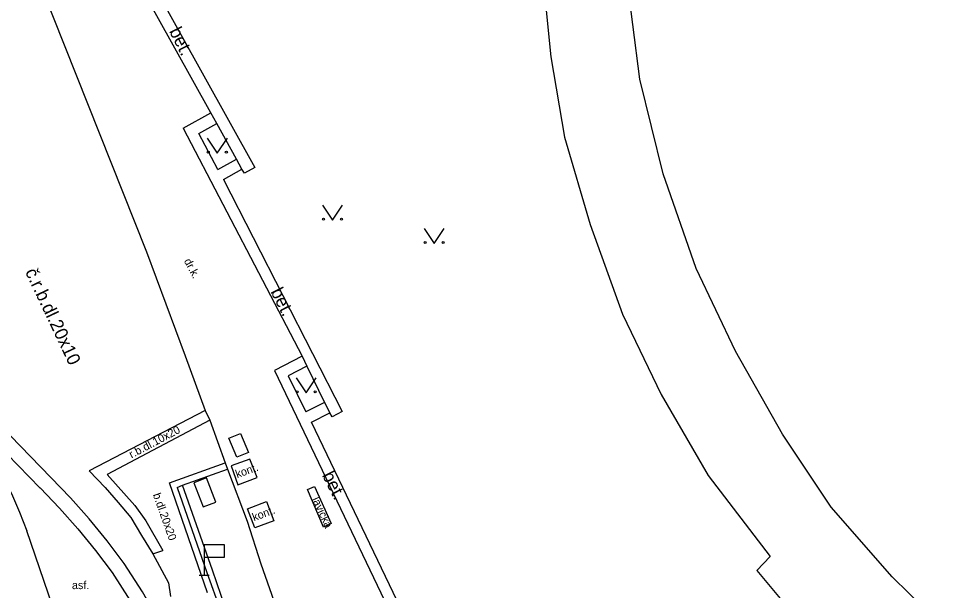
# Model space of a CAD drawing. Extents: x -600391 to -599491, y -1160176 to -1159402.
# Drawn here: x -599963.68 to -599916.73, y -1159762.76 to -1159734.28 of the extents above; entities that cross this region are included whole.
import ezdxf

# ---------------------------------------------------------------- set-up
doc = ezdxf.new("R2010")
doc.units = 0
for name, color, linetype in [('Level 10', 7, 'Continuous'), ('Level 11', 7, 'Continuous'), ('Level 13', 7, 'Continuous'), ('Level 24', 7, 'Continuous'), ('Level 25', 7, 'Continuous'), ('Level 26', 7, 'Continuous'), ('Level 34', 7, 'Continuous'), ('Level 36', 7, 'Continuous'), ('Level 40', 7, 'Continuous'), ('Level 42', 7, 'Continuous'), ('Level 53', 7, 'Continuous')]:
    doc.layers.add(name, color=color, linetype=linetype)

msp = doc.modelspace()

# ---------------------------------------------------------------- linework, layer by layer
at = {"layer": 'Level 10'}
for points in [[(-599962.58, -1159732.63), (-599957.31, -1159745.89)], [(-599957.31, -1159745.89), (-599955.38, -1159751.08), (-599954.38, -1159753.8)], [(-599954.38, -1159753.8), (-599960.18, -1159756.82), (-599959.38, -1159757.65), (-599958.73, -1159758.4), (-599958.09, -1159759.14)], [(-599958.09, -1159759.14), (-599957.56, -1159760.03)], [(-599957.56, -1159760.03), (-599956.99, -1159760.95)], [(-599956.99, -1159760.95), (-599956.22, -1159762.4), (-599956.12, -1159763.08)]]:
    msp.add_lwpolyline(points, dxfattribs=at)
at = {"layer": 'Level 11'}
for points in [[(-599952.43, -1159741.98), (-599952.55, -1159741.77), (-599952.82, -1159741.27), (-599953.81, -1159739.5), (-599954.11, -1159738.96), (-599960.3, -1159727.82)], [(-599958.22, -1159730.32), (-599951.91, -1159741.69)], [(-599937.61, -1159731.52), (-599937.15, -1159736.17)], [(-599932.71, -1159737.28), (-599933.41, -1159731.82)], [(-599937.15, -1159736.17), (-599936.47, -1159740.18)], [(-599931.55, -1159742.01), (-599932.71, -1159737.28)], [(-599955.49, -1159739.73), (-599954.11, -1159738.96)], [(-599955.49, -1159739.73), (-599949.55, -1159751.1)], [(-599954.7, -1159739.99), (-599953.81, -1159739.5)], [(-599953.75, -1159741.79), (-599954.7, -1159739.99)], [(-599936.47, -1159740.18), (-599935.18, -1159744.54)], [(-599953.75, -1159741.79), (-599952.82, -1159741.27)], [(-599953.48, -1159742.29), (-599952.55, -1159741.77)], [(-599951.91, -1159741.69), (-599952.43, -1159741.98)], [(-599929.9, -1159746.73), (-599931.55, -1159742.01)], [(-599953.48, -1159742.29), (-599947.56, -1159753.86)], [(-599935.18, -1159744.54), (-599933.57, -1159749.01)], [(-599927.94, -1159750.85), (-599929.9, -1159746.73)], [(-599933.57, -1159749.01), (-599931.65, -1159753.01)], [(-599962.08, -1159757.14), (-599968.67, -1159750.37)], [(-599925.59, -1159754.98), (-599927.94, -1159750.85)], [(-599949.55, -1159751.1), (-599950.93, -1159751.81), (-599945.45, -1159763.28), (-599945.2, -1159763.8)], [(-599949.55, -1159751.1), (-599949.31, -1159751.59), (-599948.43, -1159753.41), (-599948.17, -1159753.92)], [(-599949.31, -1159751.59), (-599950.25, -1159752.07)], [(-599950.25, -1159752.07), (-599949.36, -1159753.88)], [(-599931.65, -1159753.01), (-599929.3, -1159757.04)], [(-599954.38, -1159753.8), (-599954.16, -1159754.28), (-599953.39, -1159756.42)], [(-599948.43, -1159753.41), (-599949.36, -1159753.88)], [(-599954.16, -1159754.28), (-599959.28, -1159756.99), (-599957.89, -1159758.54), (-599957.34, -1159759.31), (-599956.49, -1159760.79)], [(-599949.09, -1159754.38), (-599948.17, -1159753.92)], [(-599947.56, -1159753.86), (-599948.06, -1159754.12), (-599948.17, -1159753.92)], [(-599943.44, -1159766.14), (-599949.09, -1159754.38)], [(-599923.17, -1159758.62), (-599925.59, -1159754.98)], [(-599954.27, -1159762.9), (-599956.17, -1159757.42), (-599953.39, -1159756.42)], [(-599953.39, -1159756.42), (-599953.27, -1159756.73)], [(-599955.79, -1159757.65), (-599955.51, -1159757.53), (-599953.27, -1159756.73)], [(-599953.27, -1159756.73), (-599952.3, -1159759.32), (-599951.61, -1159761.45), (-599949.77, -1159766.7)], [(-599929.3, -1159757.04), (-599926.2, -1159761.08)], [(-599958.43, -1159761.43), (-599959.28, -1159760.3), (-599960.17, -1159759.21), (-599961.1, -1159758.16), (-599962.08, -1159757.14)], [(-599943.42, -1159792.53), (-599943.14, -1159792.46), (-599944.14, -1159789.62), (-599946.01, -1159784.35), (-599949.02, -1159775.9), (-599951.7, -1159768.36), (-599953.37, -1159763.66), (-599954.02, -1159761.77), (-599955.51, -1159757.53)], [(-599955.79, -1159757.65), (-599954.3, -1159761.88)], [(-599920.13, -1159762.1), (-599923.17, -1159758.62)], [(-599956.99, -1159760.95), (-599956.49, -1159760.79)], [(-599926.2, -1159761.08), (-599926.87, -1159761.78)], [(-599955.32, -1159767.35), (-599955.96, -1159765.8), (-599956.7, -1159764.3), (-599957.52, -1159762.84), (-599958.43, -1159761.43)], [(-599926.87, -1159761.78), (-599923.55, -1159765.77)], [(-599954.3, -1159761.88), (-599953.62, -1159763.77), (-599951.95, -1159768.49), (-599949.27, -1159776.02), (-599946.27, -1159784.47), (-599944.41, -1159789.74), (-599943.42, -1159792.53), (-599942.77, -1159794.42), (-599943.19, -1159794.56)], [(-599916.73, -1159765.43), (-599920.13, -1159762.1)]]:
    msp.add_lwpolyline(points, dxfattribs=at)
at = {"layer": 'Level 13'}
for points in [[(-599969.22, -1159750.89), (-599962.61, -1159757.67)], [(-599965, -1159756.16), (-599964.5, -1159757.04), (-599964.05, -1159757.94), (-599963.64, -1159758.87), (-599963.28, -1159759.81)], [(-599962.61, -1159757.66), (-599961.65, -1159758.67), (-599960.73, -1159759.71), (-599959.86, -1159760.78), (-599959.02, -1159761.89)], [(-599947.03, -1159806.29), (-599948.23, -1159802.94), (-599955.48, -1159782.57), (-599960.07, -1159769.17), (-599963.28, -1159759.81)], [(-599959.02, -1159761.89), (-599958.14, -1159763.26), (-599957.34, -1159764.67), (-599956.63, -1159766.13), (-599956.01, -1159767.63)]]:
    msp.add_lwpolyline(points, dxfattribs=at)
at = {"layer": 'Level 24'}
for points in [[(-599953.2, -1159755.19), (-599952.62, -1159754.95)], [(-599952.81, -1159756.14), (-599953.2, -1159755.19)], [(-599952.62, -1159754.95), (-599952.23, -1159755.9)], [(-599952.23, -1159755.9), (-599952.81, -1159756.14)]]:
    msp.add_lwpolyline(points, dxfattribs=at)
at = {"layer": 'Level 25'}
for points in [[(-599952.16, -1159756.23), (-599953.09, -1159756.56)], [(-599953.09, -1159756.56), (-599952.75, -1159757.51)], [(-599951.8, -1159757.14), (-599952.16, -1159756.23)], [(-599952.75, -1159757.51), (-599951.8, -1159757.14)], [(-599952.27, -1159758.7), (-599951.33, -1159758.35)], [(-599951.33, -1159758.35), (-599950.97, -1159759.31)], [(-599951.91, -1159759.66), (-599952.27, -1159758.7)], [(-599950.97, -1159759.31), (-599951.91, -1159759.66)]]:
    msp.add_lwpolyline(points, dxfattribs=at)
at = {"layer": 'Level 26'}
for points in [[(-599954.32, -1159757.17), (-599954.95, -1159757.41)], [(-599954.95, -1159757.41), (-599954.49, -1159758.61)], [(-599953.86, -1159758.37), (-599954.32, -1159757.17)], [(-599954.49, -1159758.61), (-599953.86, -1159758.37)]]:
    msp.add_lwpolyline(points, dxfattribs=at)
at = {"layer": 'Level 34'}
for p, q in [((-599954.43, -1159761.11), (-599954.43, -1159762.01)), ((-599954.68, -1159762.01), (-599954.18, -1159762.01))]:
    msp.add_line(p, q, dxfattribs=at)
msp.add_lwpolyline([(-599954.43, -1159761.11), (-599953.43, -1159761.11), (-599953.43, -1159760.51), (-599954.43, -1159760.51)], close=True, dxfattribs=at)
at = {"layer": 'Level 36'}
for points in [[(-599954.28, -1159740.23), (-599953.78, -1159740.98), (-599953.28, -1159740.23)], [(-599948.54, -1159743.57), (-599948.04, -1159744.32), (-599947.54, -1159743.57)], [(-599943.47, -1159744.73), (-599942.97, -1159745.48), (-599942.47, -1159744.73)], [(-599949.85, -1159752.17), (-599949.35, -1159752.92), (-599948.85, -1159752.17)]]:
    msp.add_lwpolyline(points, dxfattribs=at)
for centre in [(-599954.23, -1159740.93), (-599953.331, -1159740.93), (-599948.49, -1159744.27), (-599947.591, -1159744.27), (-599943.42, -1159745.43), (-599942.521, -1159745.43), (-599949.8, -1159752.87), (-599948.901, -1159752.87)]:
    msp.add_circle(centre, 0.05, dxfattribs=at)
at = {"layer": 'Level 53'}
for points in [[(-599949.29, -1159757.75), (-599948.94, -1159757.6)], [(-599948.94, -1159757.6), (-599948.1, -1159759.44)], [(-599948.49, -1159759.62), (-599949.29, -1159757.75)], [(-599948.1, -1159759.44), (-599948.49, -1159759.62)]]:
    msp.add_lwpolyline(points, dxfattribs=at)

# ---------------------------------------------------------------- texts
at = {"layer": 'Level 40'}
for s, height, rotation, p in [('bet.', 0.65, 296.8068, (-599956.2, -1159734.89)), ('dr.k.', 0.4, 298, (-599955.46, -1159746.35)), ('č.r.b.dl.20x10', 0.65, 295.314, (-599963.38, -1159746.89)), ('bet.', 0.65, 296.8068, (-599951.14, -1159747.88)), ('r.b.dl.10x20', 0.4, 27.8921, (-599958.06, -1159756.2)), ('bet.', 0.65, 296.8068, (-599948.57, -1159757.03)), ('b.dl.20x20', 0.4, 289.5884, (-599957, -1159758))]:
    msp.add_text(s, height=height, rotation=rotation, dxfattribs=at).set_placement(p)
msp.add_text('asf.', height=0.4, dxfattribs=at).set_placement((-599961.03, -1159762.71))
at = {"layer": 'Level 42'}
for s, rotation, p in [('kont.', 19.5367, (-599952.79, -1159757.18)), ('lavička', 294.8765, (-599949.07, -1159758.23)), ('kont.', 20.4223, (-599951.95, -1159759.33))]:
    msp.add_text(s, height=0.4, rotation=rotation, dxfattribs=at).set_placement(p)

doc.saveas('drawing.dxf')
